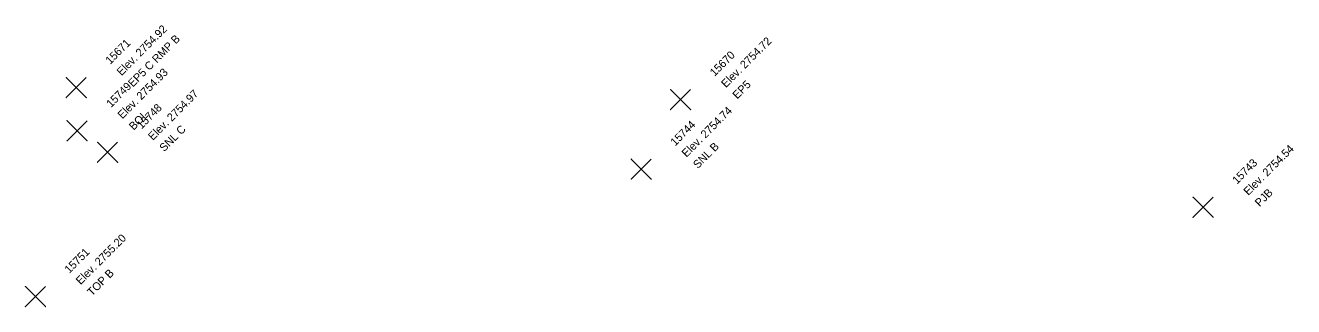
# Model space of a CAD drawing. Extents: x 2493999 to 2503109, y 700767 to 706646.
# Drawn here: x 2502242.22 to 2502261.24, y 704032.76 to 704036.98 of the extents above; entities that cross this region are included whole.
import ezdxf

# ---------------------------------------------------------------- set-up
doc = ezdxf.new("R2010")
doc.units = 0
doc.layers.add('ALG_CL_BLUE_Horiz', color=7, linetype='Continuous')
doc.layers.add('DES_SURFACE_Existing-Ground', color=7, linetype='Continuous')

msp = doc.modelspace()

# ---------------------------------------------------------------- linework, layer by layer
at = {"layer": 'ALG_CL_BLUE_Horiz'}
for points in [[(2502242.98, 704036.045), (2502242.83, 704036.195), (2502242.98, 704036.045), (2502242.83, 704035.895), (2502242.98, 704036.045), (2502243.13, 704035.895), (2502242.98, 704036.045), (2502243.13, 704036.195)], [(2502252.046, 704035.865), (2502251.896, 704036.015), (2502252.046, 704035.865), (2502251.896, 704035.715), (2502252.046, 704035.865), (2502252.196, 704035.715), (2502252.046, 704035.865), (2502252.196, 704036.015)], [(2502242.993, 704035.397), (2502242.843, 704035.547), (2502242.993, 704035.397), (2502242.843, 704035.247), (2502242.993, 704035.397), (2502243.143, 704035.247), (2502242.993, 704035.397), (2502243.143, 704035.547)], [(2502243.45, 704035.076), (2502243.3, 704035.226), (2502243.45, 704035.076), (2502243.3, 704034.926), (2502243.45, 704035.076), (2502243.6, 704034.926), (2502243.45, 704035.076), (2502243.6, 704035.226)], [(2502251.455, 704034.823), (2502251.305, 704034.973), (2502251.455, 704034.823), (2502251.305, 704034.673), (2502251.455, 704034.823), (2502251.605, 704034.673), (2502251.455, 704034.823), (2502251.605, 704034.973)], [(2502259.882, 704034.251), (2502259.732, 704034.401), (2502259.882, 704034.251), (2502259.732, 704034.101), (2502259.882, 704034.251), (2502260.032, 704034.101), (2502259.882, 704034.251), (2502260.032, 704034.401)], [(2502242.367, 704032.914), (2502242.217, 704033.064), (2502242.367, 704032.914), (2502242.217, 704032.764), (2502242.367, 704032.914), (2502242.517, 704032.764), (2502242.367, 704032.914), (2502242.517, 704033.064)]]:
    msp.add_lwpolyline(points, dxfattribs=at)

# ---------------------------------------------------------------- texts
at = {"layer": 'DES_SURFACE_Existing-Ground'}
for s, p in [('Elev. 2754.92', (2502243.659, 704036.215)), ('EP5 C RMP B', (2502243.829, 704036.045)), ('15671', (2502243.489, 704036.384)), ('Elev. 2754.72', (2502252.725, 704036.035)), ('15670', (2502252.555, 704036.204)), ('Elev. 2754.93', (2502243.672, 704035.567)), ('15749', (2502243.502, 704035.736)), ('EP5', (2502252.895, 704035.865)), ('Elev. 2754.97', (2502244.129, 704035.246)), ('BOL', (2502243.842, 704035.397)), ('15748', (2502243.959, 704035.415)), ('Elev. 2754.74', (2502252.134, 704034.993)), ('SNL C', (2502244.299, 704035.076)), ('15744', (2502251.964, 704035.162)), ('SNL B', (2502252.304, 704034.823)), ('Elev. 2754.54', (2502260.561, 704034.421)), ('15743', (2502260.391, 704034.59)), ('PJB', (2502260.731, 704034.251)), ('Elev. 2755.20', (2502243.046, 704033.084)), ('15751', (2502242.876, 704033.253)), ('TOP B', (2502243.216, 704032.914))]:
    msp.add_text(s, height=0.12, rotation=45, dxfattribs=at).set_placement(p)

doc.saveas('drawing.dxf')
